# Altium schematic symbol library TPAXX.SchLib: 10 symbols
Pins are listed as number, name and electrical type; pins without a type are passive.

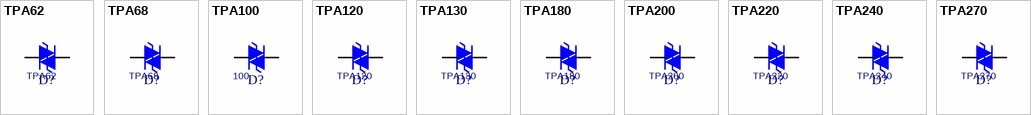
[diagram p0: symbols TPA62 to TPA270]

## TPA62
designator D?
footprint ST_DO15B
pins: 1, 2

## TPA68
designator D?
footprint ST_DO15B
pins: 1, 2

## TPA100
designator D?, comment 100
footprint ST_DO15B
pins: 1, 2

## TPA120
designator D?
footprint ST_DO15B
pins: 1, 2

## TPA130
designator D?
footprint ST_DO15B
pins: 1, 2

## TPA180
designator D?
footprint ST_DO15B
pins: 1, 2

## TPA200
designator D?
footprint ST_DO15B
pins: 1, 2

## TPA220
designator D?
footprint ST_DO15B
pins: 1, 2

## TPA240
designator D?
footprint ST_DO15B
pins: 1, 2

## TPA270
designator D?
footprint ST_DO15B
pins: 1, 2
